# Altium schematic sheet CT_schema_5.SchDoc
size 266 x 267 mm
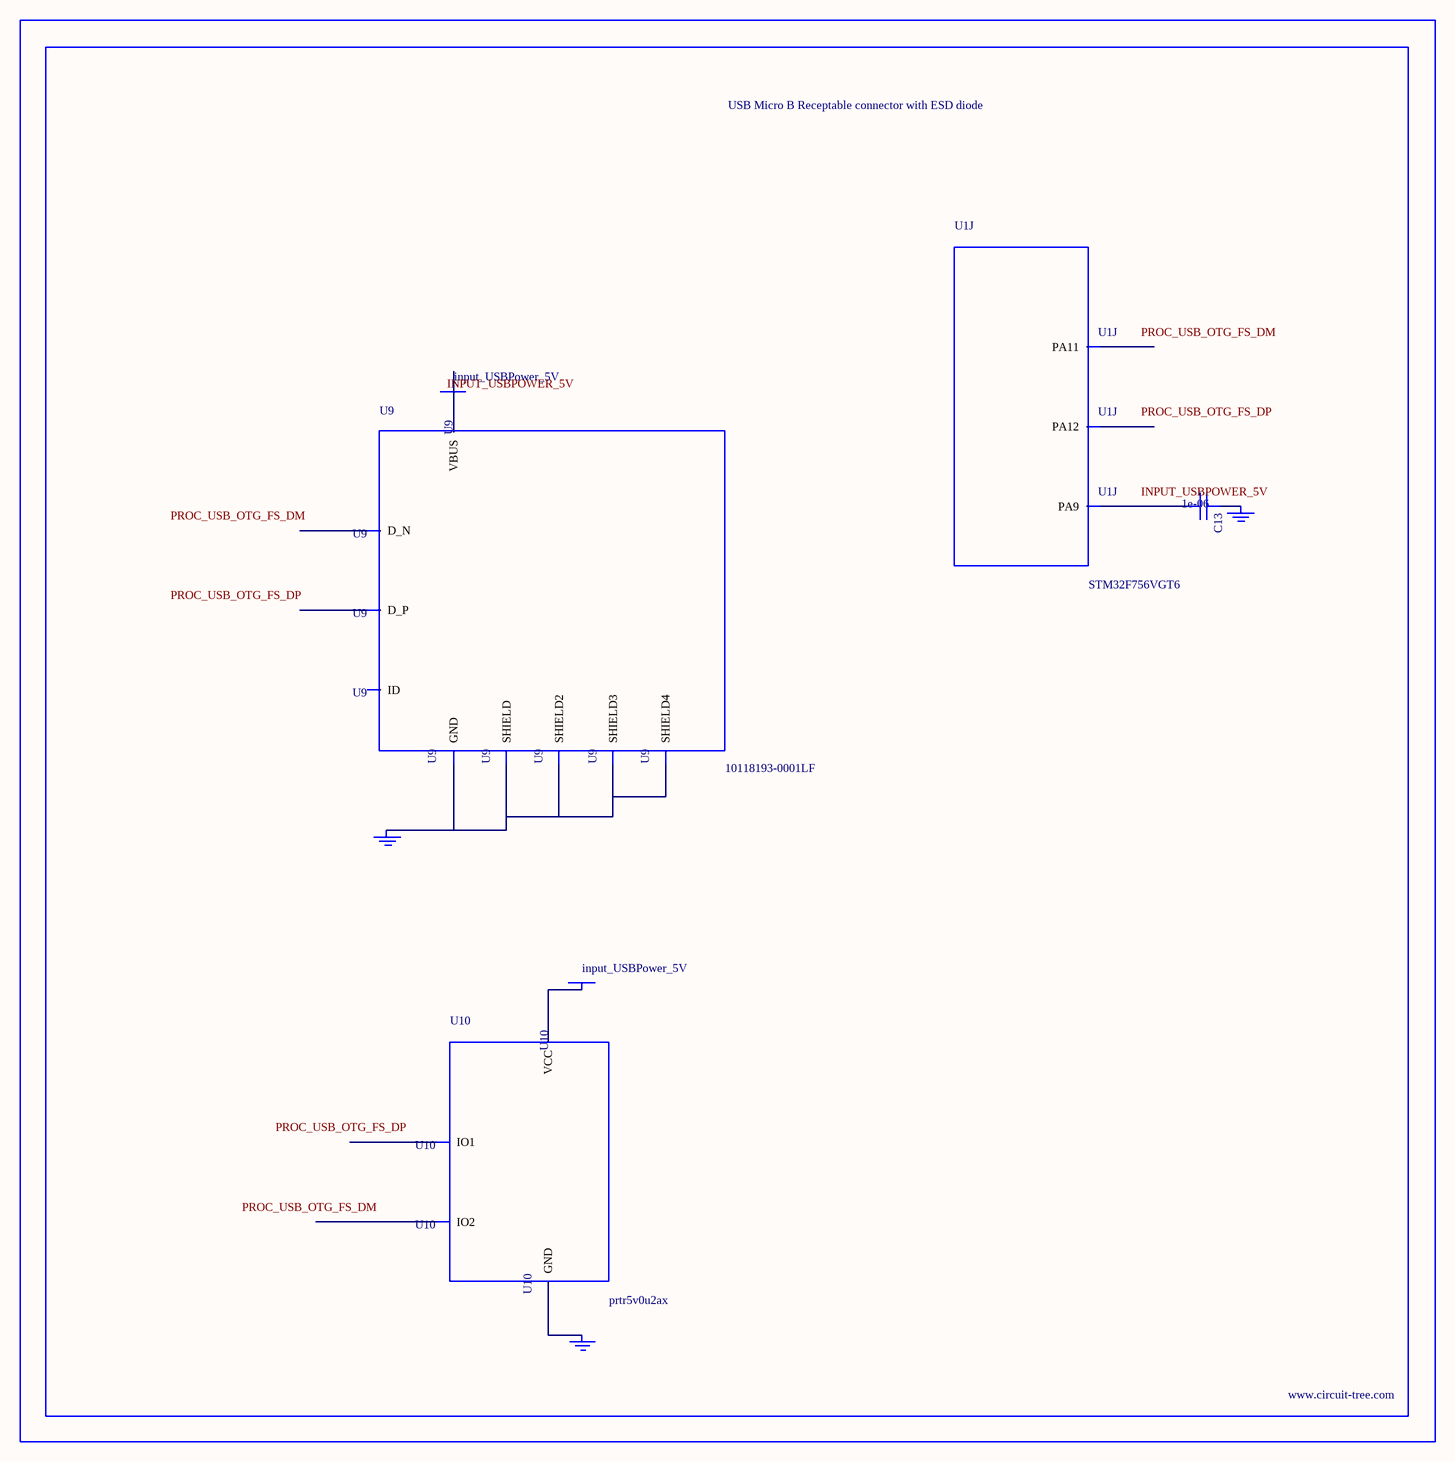
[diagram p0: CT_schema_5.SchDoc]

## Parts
BORDER4  (no value)
C13  1e-06  [C0603]
GND_INSTANCE_4_0  (no value)
GND_INSTANCE_4_1  (no value)
GND_INSTANCE_4_2  (no value)
POWER_INSTANCE_4_0  input_USBPower_5V
POWER_INSTANCE_4_1  input_USBPower_5V
U1  STM32F756VGT6  [LQFP100]  (part J of 10)
U9  10118193-0001LF  [FCI_10118193-0001LF]
U10  prtr5v0u2ax  [SOT143B]

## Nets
NetC13_1: C13.1 GND_INSTANCE_4_1.0(GND)
NetC13_2: C13.2 U1.68(PA9)
NetGND_INSTANCE_4_0_0: GND_INSTANCE_4_0.0(GND) U9.5(GND) U9.6(SHIELD) U9.7(SHIELD2) U9.8(SHIELD3) U9.9(SHIELD4)
NetGND_INSTANCE_4_2_0: GND_INSTANCE_4_2.0(GND) U10.1(GND)
NetPOWER_INSTANCE_4_0_0: POWER_INSTANCE_4_0.0(PWR) U9.1(VBUS)
NetPOWER_INSTANCE_4_1_0: POWER_INSTANCE_4_1.0(PWR) U10.4(VCC)

Not connected (* = marked no-connect by the designer): U1 70(PA11) 71(PA12); U9 2(D_N) 3(D_P) 4(ID); U10 2(IO1) 3(IO2)

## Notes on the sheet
- Labels drawn without touching a wire or pin: INPUT_USBPOWER_5V, PROC_USB_OTG_FS_DM, PROC_USB_OTG_FS_DP

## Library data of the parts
BORDER4 = BORDER_PAGE4
C13 = C0603C105K3RACTU
GND_INSTANCE_4_0-GND_INSTANCE_4_2 = GND
POWER_INSTANCE_4_0 POWER_INSTANCE_4_1 = PWR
